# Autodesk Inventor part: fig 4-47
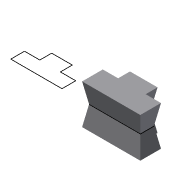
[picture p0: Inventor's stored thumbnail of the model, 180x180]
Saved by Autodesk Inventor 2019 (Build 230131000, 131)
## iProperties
Created: 2004-05
Part Number: fig 4-47
Document SubType Name: Modeling
Designer: CADCIM Technologies
Manufacturer: Standard
Standards Organization: Custom
Density: 1 g/cm^3
Material: Generic
Appearance: Default
Author: CADCIM Technologies
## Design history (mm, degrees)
sketch "Sketch1"
  geometry: L1 (31.783, 34.561)-(31.783, 22.933); L2 (31.783, 22.933)-(16.796, 22.933); L3 (16.796, 22.933)-(16.796, 9.496); L4 (16.796, 9.496)-(66.925, 9.496); L5 (66.925, 9.496)-(66.925, 22.933); L6 (66.925, 22.933)-(51.938, 22.933); L7 (51.938, 22.933)-(51.938, 34.561); L8 (51.938, 34.561)-(31.783, 34.561); L9 (-45.013, 34.561)-(-45.013, 22.933); L10 (-45.013, 22.933)-(-60, 22.933); L11 (-60, 22.933)-(-60, 9.496); L12 (-60, 9.496)-(-9.871, 9.496); L13 (-9.871, 9.496)-(-9.871, 22.933); L14 (-9.871, 22.933)-(-24.858, 22.933); L15 (-24.858, 22.933)-(-24.858, 34.561); L16 (-24.858, 34.561)-(-45.013, 34.561)
  constraints: 32 end point, 10 parallel, 4 equal length, 2 collinear, 2 perpendicular, 2 vertical
extrude "Extrusion2" new body sketch "Sketch1" stored distance "d2" = 38.75; taper "d3" = 10 deg
body "Solid2"
